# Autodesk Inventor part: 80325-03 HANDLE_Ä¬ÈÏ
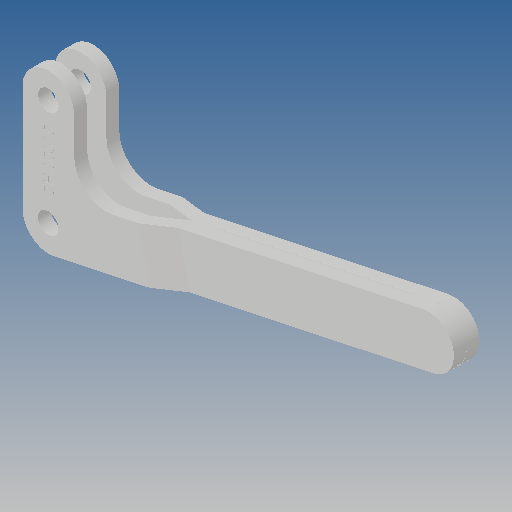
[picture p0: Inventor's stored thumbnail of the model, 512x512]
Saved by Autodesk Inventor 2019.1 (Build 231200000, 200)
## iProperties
Created: 2010-06
Part Number: 80325-03 HANDLE_Ä¬ÈÏ
Material: Ogólny
Document SubType Name: Modeling
Designer: CADENGINEERING4
Density: 1 g/cm^3
Appearance: Domyślna
Author: CADENGINEERING4
Revision Number: ÈÎºÎ
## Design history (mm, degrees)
feature "NONE"
feature "NONE:1"
node "Bryła1"
node "Bryła2"
